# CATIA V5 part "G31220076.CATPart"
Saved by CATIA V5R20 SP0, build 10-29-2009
Part number: G31220076
Revision: 13
Definition: design
Nomenclature: G31220076
Source: made
Description: NOT SPECIFIED
Bounding box of the stored display mesh (mm): x -8 to 76, y -15.5 to 15.5, z -15.5 to 15.5
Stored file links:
  C:\Users\Raffaele\Desktop\3D X SITO CF\BOLEX\23-BUSH REF 312\G31220076.CATPart

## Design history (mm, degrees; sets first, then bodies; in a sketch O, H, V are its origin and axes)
Body1 "MANIFOLD_SOLID_BREP #19379" (main body)
  Solid1: solid without history
Body2 "MANIFOLD_SOLID_BREP #19526"
  Solid2: solid without history
Body3 "MANIFOLD_SOLID_BREP #19673"
  Solid3: solid without history
Body4 "MANIFOLD_SOLID_BREP #19820"
  Solid4: solid without history
Body5 "MANIFOLD_SOLID_BREP #19967"
  Solid5: solid without history
Body6 "MANIFOLD_SOLID_BREP #20116"
  Solid6: solid without history
Body7 "MANIFOLD_SOLID_BREP #20265"
  Solid7: solid without history
Body8 "MANIFOLD_SOLID_BREP #20414"
  Solid8: solid without history
Body9 "MANIFOLD_SOLID_BREP #20563"
  Solid9: solid without history
Body10 "MANIFOLD_SOLID_BREP #20712"
  Solid10: solid without history
Body11 "MANIFOLD_SOLID_BREP #20861"
  Solid11: solid without history
Body12 "MANIFOLD_SOLID_BREP #21010"
  Solid12: solid without history
Body13 "MANIFOLD_SOLID_BREP #21159"
  Solid13: solid without history
Body14 "MANIFOLD_SOLID_BREP #21308"
  Solid14: solid without history
Body15 "MANIFOLD_SOLID_BREP #21457"
  Solid15: solid without history
Body16 "MANIFOLD_SOLID_BREP #21606"
  Solid16: solid without history
Body17 "MANIFOLD_SOLID_BREP #21755"
  Solid17: solid without history
Body18 "MANIFOLD_SOLID_BREP #21904"
  Solid18: solid without history
Body19 "MANIFOLD_SOLID_BREP #22053"
  Solid19: solid without history
Body20 "MANIFOLD_SOLID_BREP #22202"
  Solid20: solid without history
Body21 "MANIFOLD_SOLID_BREP #22351"
  Solid21: solid without history
Body22 "MANIFOLD_SOLID_BREP #22500"
  Solid22: solid without history
Body23 "MANIFOLD_SOLID_BREP #22649"
  Solid23: solid without history
Body24 "MANIFOLD_SOLID_BREP #22798"
  Solid24: solid without history
Body25 "MANIFOLD_SOLID_BREP #22947"
  Solid25: solid without history
Body26 "MANIFOLD_SOLID_BREP #23096"
  Solid26: solid without history
Body27 "MANIFOLD_SOLID_BREP #23245"
  Solid27: solid without history
Body28 "MANIFOLD_SOLID_BREP #23394"
  Solid28: solid without history
Body29 "MANIFOLD_SOLID_BREP #23543"
  Solid29: solid without history
Body30 "MANIFOLD_SOLID_BREP #23692"
  Solid30: solid without history
Body31 "MANIFOLD_SOLID_BREP #23841"
  Solid31: solid without history
Body32 "MANIFOLD_SOLID_BREP #23988"
  Solid32: solid without history
Body33 "MANIFOLD_SOLID_BREP #24135"
  Solid33: solid without history
Body34 "MANIFOLD_SOLID_BREP #24284"
  Solid34: solid without history
Body35 "MANIFOLD_SOLID_BREP #24433"
  Solid35: solid without history
Body36 "MANIFOLD_SOLID_BREP #24582"
  Solid36: solid without history
Body37 "MANIFOLD_SOLID_BREP #24731"
  Solid37: solid without history
Body38 "MANIFOLD_SOLID_BREP #24880"
  Solid38: solid without history
Body39 "MANIFOLD_SOLID_BREP #25029"
  Solid39: solid without history
Body40 "MANIFOLD_SOLID_BREP #25178"
  Solid40: solid without history
Body41 "MANIFOLD_SOLID_BREP #25327"
  Solid41: solid without history
Body42 "MANIFOLD_SOLID_BREP #25476"
  Solid42: solid without history
Body43 "MANIFOLD_SOLID_BREP #25625"
  Solid43: solid without history
Body44 "MANIFOLD_SOLID_BREP #25774"
  Solid44: solid without history
Body45 "MANIFOLD_SOLID_BREP #25923"
  Solid45: solid without history
Body46 "MANIFOLD_SOLID_BREP #26072"
  Solid46: solid without history
Body47 "MANIFOLD_SOLID_BREP #26221"
  Solid47: solid without history
Body48 "MANIFOLD_SOLID_BREP #26370"
  Solid48: solid without history
Body49 "MANIFOLD_SOLID_BREP #26519"
  Solid49: solid without history
Body50 "MANIFOLD_SOLID_BREP #26668"
  Solid50: solid without history
Body51 "MANIFOLD_SOLID_BREP #26817"
  Solid51: solid without history
Body52 "MANIFOLD_SOLID_BREP #26966"
  Solid52: solid without history
Body53 "MANIFOLD_SOLID_BREP #27115"
  Solid53: solid without history
Body54 "MANIFOLD_SOLID_BREP #27264"
  Solid54: solid without history
Body55 "MANIFOLD_SOLID_BREP #27413"
  Solid55: solid without history
Body56 "MANIFOLD_SOLID_BREP #27560"
  Solid56: solid without history
Body57 "MANIFOLD_SOLID_BREP #27707"
  Solid57: solid without history
Body58 "MANIFOLD_SOLID_BREP #27856"
  Solid58: solid without history
Body59 "MANIFOLD_SOLID_BREP #28005"
  Solid59: solid without history
Body60 "MANIFOLD_SOLID_BREP #28154"
  Solid60: solid without history
Body61 "MANIFOLD_SOLID_BREP #28303"
  Solid61: solid without history
Body62 "MANIFOLD_SOLID_BREP #28452"
  Solid62: solid without history
Body63 "MANIFOLD_SOLID_BREP #28601"
  Solid63: solid without history
Body64 "MANIFOLD_SOLID_BREP #28748"
  Solid64: solid without history
Body65 "MANIFOLD_SOLID_BREP #28895"
  Solid65: solid without history
Body66 "MANIFOLD_SOLID_BREP #29044"
  Solid66: solid without history
Body67 "MANIFOLD_SOLID_BREP #29193"
  Solid67: solid without history
Body68 "MANIFOLD_SOLID_BREP #29342"
  Solid68: solid without history
Body69 "MANIFOLD_SOLID_BREP #29491"
  Solid69: solid without history
Body70 "MANIFOLD_SOLID_BREP #29640"
  Solid70: solid without history
Body71 "MANIFOLD_SOLID_BREP #29789"
  Solid71: solid without history
Body72 "MANIFOLD_SOLID_BREP #29938"
  Solid72: solid without history
Body73 "MANIFOLD_SOLID_BREP #30087"
  Solid73: solid without history
Body74 "MANIFOLD_SOLID_BREP #30236"
  Solid74: solid without history
Body75 "MANIFOLD_SOLID_BREP #30385"
  Solid75: solid without history
Body76 "MANIFOLD_SOLID_BREP #30534"
  Solid76: solid without history
Body77 "MANIFOLD_SOLID_BREP #30683"
  Solid77: solid without history
Body78 "MANIFOLD_SOLID_BREP #30832"
  Solid78: solid without history
Body79 "MANIFOLD_SOLID_BREP #30981"
  Solid79: solid without history
Body80 "MANIFOLD_SOLID_BREP #31130"
  Solid80: solid without history
Body81 "MANIFOLD_SOLID_BREP #31279"
  Solid81: solid without history
Body82 "MANIFOLD_SOLID_BREP #31428"
  Solid82: solid without history
Body83 "MANIFOLD_SOLID_BREP #31577"
  Solid83: solid without history
Body84 "MANIFOLD_SOLID_BREP #31726"
  Solid84: solid without history
Body85 "MANIFOLD_SOLID_BREP #31875"
  Solid85: solid without history
Body86 "MANIFOLD_SOLID_BREP #32022"
  Solid86: solid without history
Body87 "MANIFOLD_SOLID_BREP #32169"
  Solid87: solid without history
Body88 "MANIFOLD_SOLID_BREP #32316"
  Solid88: solid without history
Body89 "MANIFOLD_SOLID_BREP #32463"
  Solid89: solid without history
Body90 "MANIFOLD_SOLID_BREP #32612"
  Solid90: solid without history
Body91 "MANIFOLD_SOLID_BREP #32761"
  Solid91: solid without history
Body92 "MANIFOLD_SOLID_BREP #32910"
  Solid92: solid without history
Body93 "MANIFOLD_SOLID_BREP #33059"
  Solid93: solid without history
Body94 "MANIFOLD_SOLID_BREP #33208"
  Solid94: solid without history
Body95 "MANIFOLD_SOLID_BREP #33357"
  Solid95: solid without history
Body96 "MANIFOLD_SOLID_BREP #33506"
  Solid96: solid without history
Body97 "MANIFOLD_SOLID_BREP #33655"
  Solid97: solid without history
Body98 "MANIFOLD_SOLID_BREP #33804"
  Solid98: solid without history
Body99 "MANIFOLD_SOLID_BREP #33953"
  Solid99: solid without history
Body100 "MANIFOLD_SOLID_BREP #34102"
  Solid100: solid without history
Body101 "MANIFOLD_SOLID_BREP #34251"
  Solid101: solid without history
Body102 "MANIFOLD_SOLID_BREP #34400"
  Solid102: solid without history
Body103 "MANIFOLD_SOLID_BREP #34549"
  Solid103: solid without history
Body104 "MANIFOLD_SOLID_BREP #34698"
  Solid104: solid without history
Body105 "MANIFOLD_SOLID_BREP #34847"
  Solid105: solid without history
Body106 "MANIFOLD_SOLID_BREP #34996"
  Solid106: solid without history
Body107 "MANIFOLD_SOLID_BREP #35145"
  Solid107: solid without history
Body108 "MANIFOLD_SOLID_BREP #35294"
  Solid108: solid without history
Body109 "MANIFOLD_SOLID_BREP #35443"
  Solid109: solid without history
Body110 "MANIFOLD_SOLID_BREP #35592"
  Solid110: solid without history
Body111 "MANIFOLD_SOLID_BREP #35741"
  Solid111: solid without history
Body112 "MANIFOLD_SOLID_BREP #35888"
  Solid112: solid without history
Body113 "MANIFOLD_SOLID_BREP #36035"
  Solid113: solid without history
Body114 "MANIFOLD_SOLID_BREP #36184"
  Solid114: solid without history
Body115 "MANIFOLD_SOLID_BREP #36333"
  Solid115: solid without history
Body116 "MANIFOLD_SOLID_BREP #36482"
  Solid116: solid without history
Body117 "MANIFOLD_SOLID_BREP #36631"
  Solid117: solid without history
Body118 "MANIFOLD_SOLID_BREP #36780"
  Solid118: solid without history
Body119 "MANIFOLD_SOLID_BREP #36929"
  Solid119: solid without history
Body120 "MANIFOLD_SOLID_BREP #37078"
  Solid120: solid without history
Body121 "MANIFOLD_SOLID_BREP #37227"
  Solid121: solid without history
Body122 "MANIFOLD_SOLID_BREP #37376"
  Solid122: solid without history
Body123 "MANIFOLD_SOLID_BREP #37525"
  Solid123: solid without history
Body124 "MANIFOLD_SOLID_BREP #37674"
  Solid124: solid without history
Body125 "MANIFOLD_SOLID_BREP #37823"
  Solid125: solid without history
Body126 "MANIFOLD_SOLID_BREP #37972"
  Solid126: solid without history
Body127 "MANIFOLD_SOLID_BREP #38121"
  Solid127: solid without history
Body128 "MANIFOLD_SOLID_BREP #38268"
  Solid128: solid without history
Body129 "MANIFOLD_SOLID_BREP #38415"
  Solid129: solid without history
Body130 "MANIFOLD_SOLID_BREP #38564"
  Solid130: solid without history
Body131 "MANIFOLD_SOLID_BREP #38713"
  Solid131: solid without history
Body132 "MANIFOLD_SOLID_BREP #38862"
  Solid132: solid without history
Body133 "MANIFOLD_SOLID_BREP #39011"
  Solid133: solid without history
Body134 "MANIFOLD_SOLID_BREP #39160"
  Solid134: solid without history
Body135 "MANIFOLD_SOLID_BREP #39309"
  Solid135: solid without history
Body136 "MANIFOLD_SOLID_BREP #39458"
  Solid136: solid without history
Body137 "MANIFOLD_SOLID_BREP #39607"
  Solid137: solid without history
